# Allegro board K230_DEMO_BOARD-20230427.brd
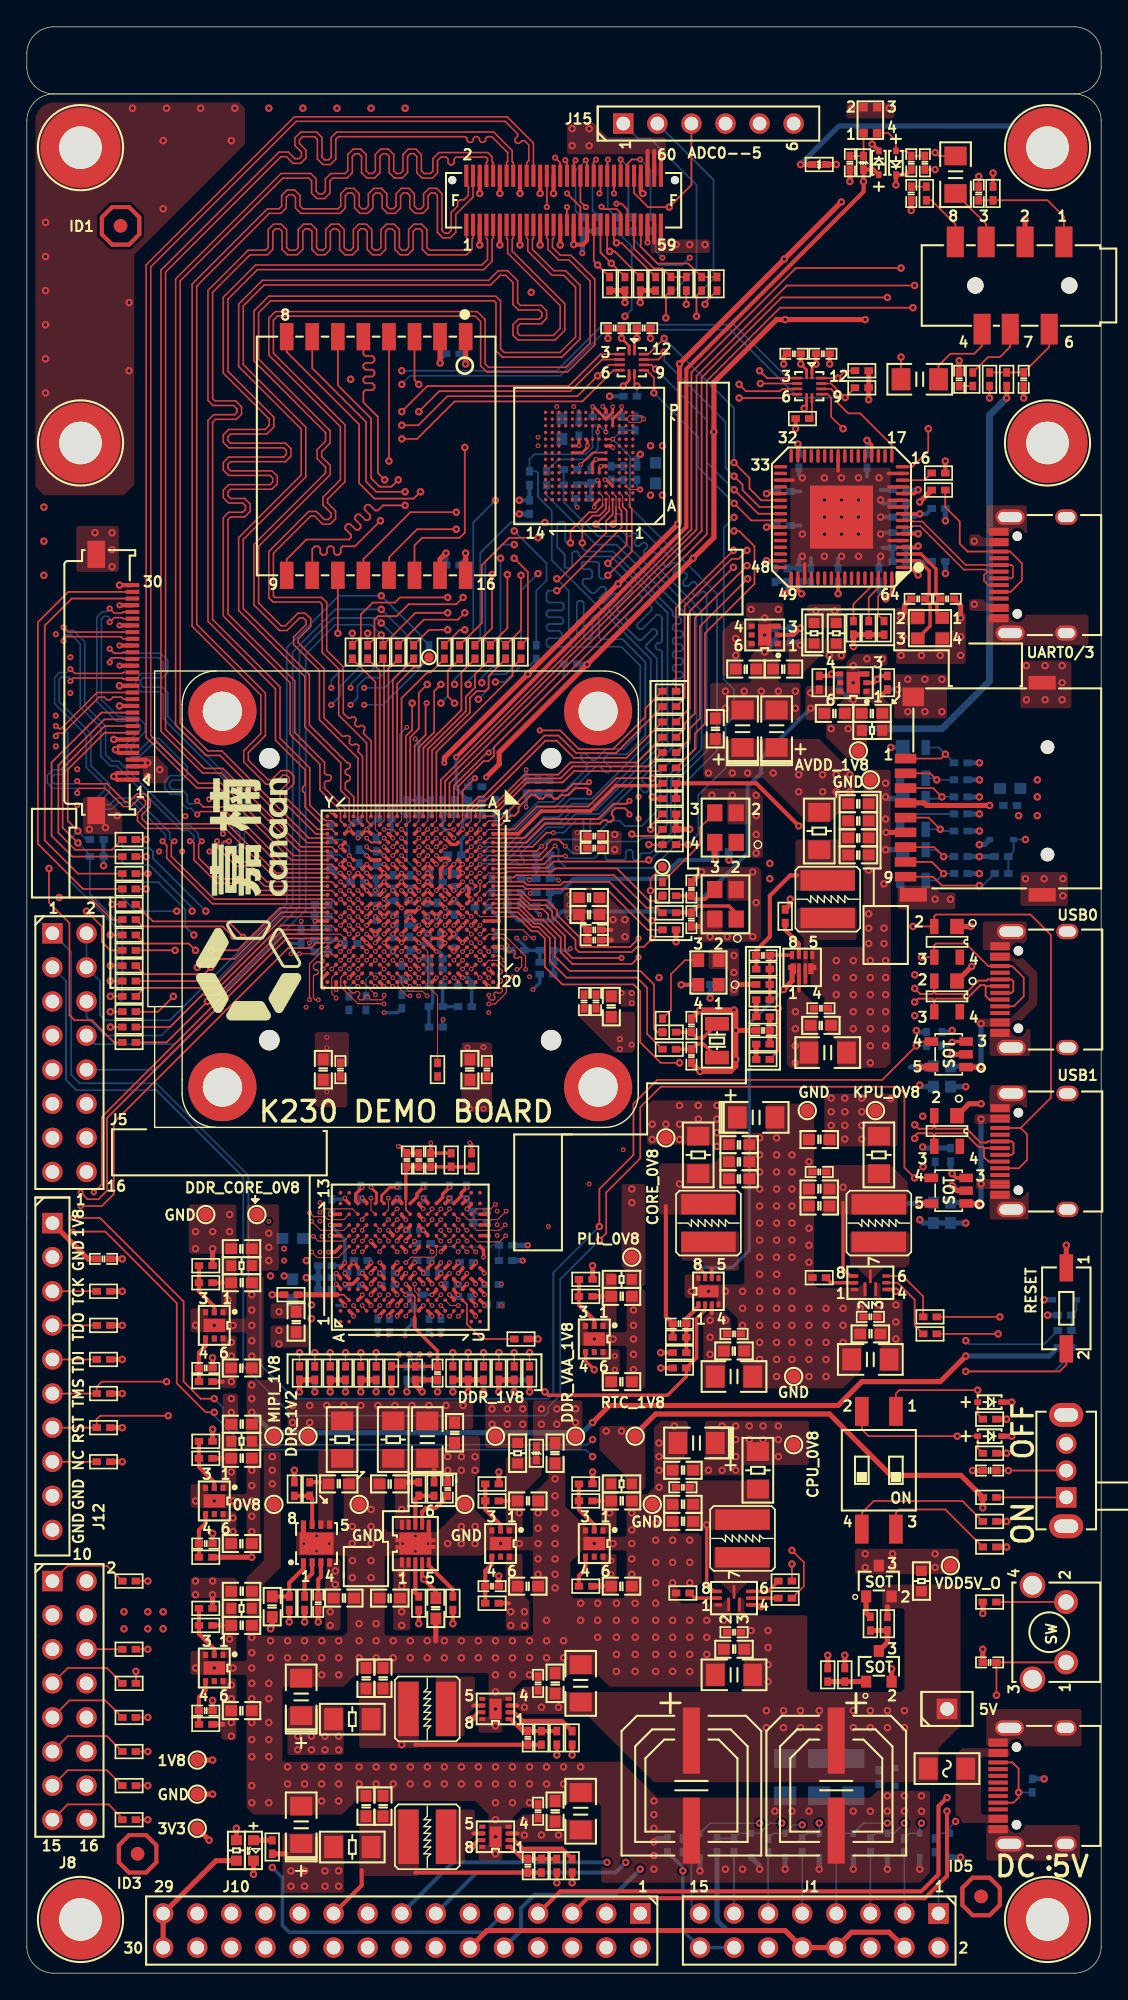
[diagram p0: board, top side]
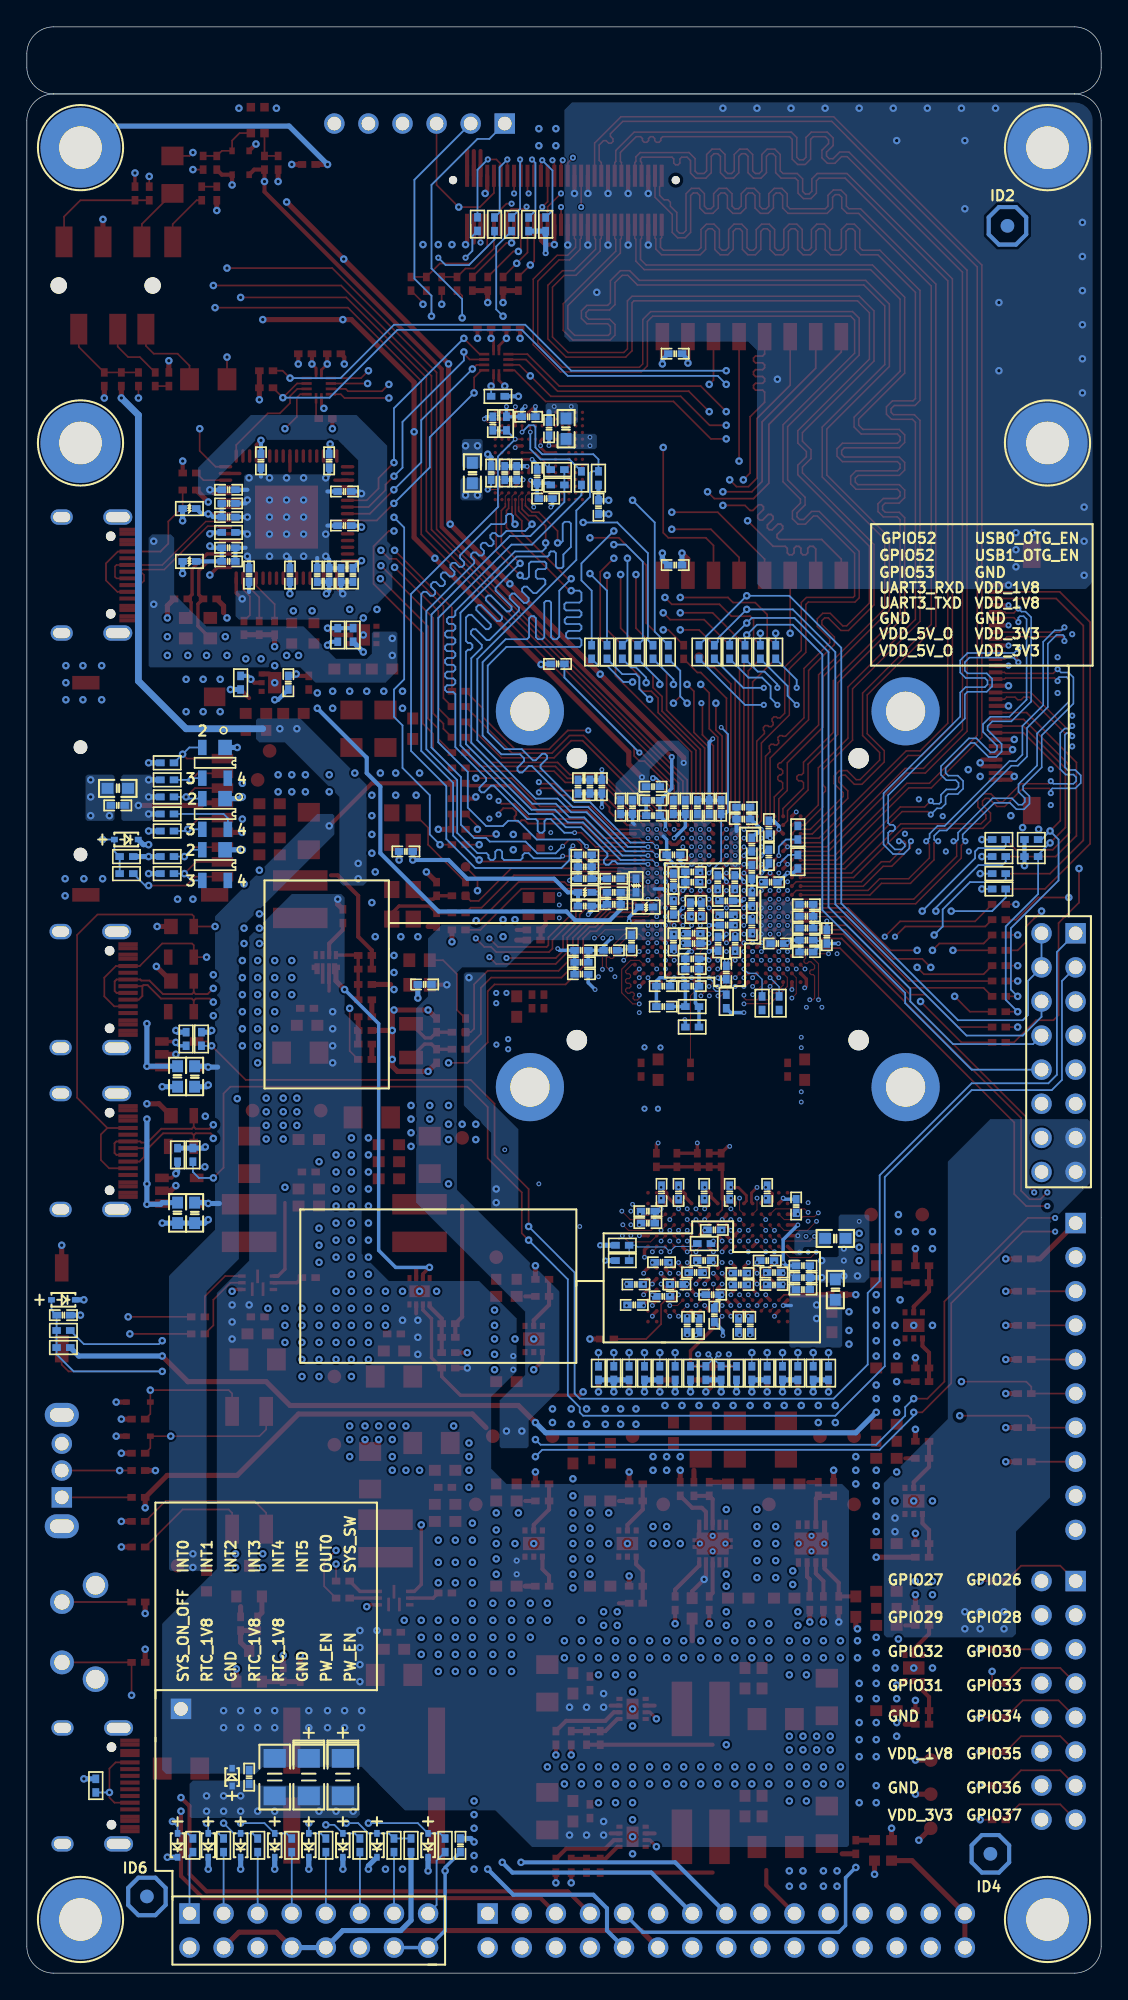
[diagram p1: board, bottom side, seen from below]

Outline 80.07 x 145 mm; copper layers: TOP, GND02, ART03, POWER04, GND05, ART06, GND07, BOTTOM. Coordinates in mm from the lower left corner of the outline.
Outline path: 2,140 arc(0.59,139.41) 0,138 0,2 arc(0.59,0.59) 2,0 78.07,0 arc(79.48,0.59) 80.07,2 80.07,138 arc(79.48,139.41) 78.07,140 ; 2,140 arc(0.59,140.59) 0,142 0,143 arc(0.59,144.41) 2,145 78.07,145 arc(79.48,144.41) 80.07,143 80.07,142 arc(79.48,140.59) 78.07,140 ; 2,140 78.07,140 ; 2,140 78.07,140

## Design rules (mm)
net group 3D_CTRL_IN: nets 3D_CTRL_IN N21013370
net group 3D_CTRL_OUT1: nets 3D_CTRL_OUT1 N21013374
net group 3D_CTRL_OUT2: nets 3D_CTRL_OUT2 N21013378
net group ADC_2: nets ADC_2 N21252475
net group ADC_3: nets ADC_3 N21252478
net group ADC_4: nets ADC_4 N21252481
net group BUS-ADD: nets LP3_CA0 LP3_CA1
net group DIFF100: nets DEBUG_DM DEBUG_DP
net group DL_M_CLK2: nets DL_M_CLK2 N21014154
net group DL_M_CLK3: nets DL_M_CLK3 N21014156
net group DP_M_CLK1: nets DP_M_CLK1 N21013382
net group EMMC_CLK: nets EMMC_CLK N21433380
net group EMMC_STROBE: nets EMMC_STROBE N21377535
net group GPIO26: nets GPIO26 N21015638
net group GPIO27: nets GPIO27 N21015640
net group GPIO28: nets GPIO28 N21015650
net group GPIO32: nets GPIO32 N21015658
net group GPIO33: nets GPIO33 N21015660
net group GPIO34: nets GPIO34 N21015662
net group GPIO35: nets GPIO35 N21015664
net group GPIO36: nets GPIO36 N21015666
net group GPIO37: nets GPIO37 N21015668
net group GPIO47: nets GPIO47 N21014397
net group GPIO48: nets GPIO48 N21014399
net group GPIO49: nets GPIO49 N21014401
net group GPIO52: nets GPIO52 N21015121
net group GPIO60_3V3: nets GPIO60_3V3 N21015137
net group GPIO61_3V3: nets GPIO61_3V3 N21015139
net group I2C3_SCL: nets I2C3_SCL N21014391
net group I2C3_SDA: nets I2C3_SDA N21014393
net group LP3_ODT: nets LP3_ODT N21376209
net group MMC1_CLK: nets MMC1_CLK N21015127
net group MMC1_CMD: nets MMC1_CMD N21015125
net group MMC1_D0: nets MMC1_D0 N21015129
net group MMC1_D1: nets MMC1_D1 N21015131
net group MMC1_D2: nets MMC1_D2 N21015133
net group MMC1_D3: nets MMC1_D3 N21015135
net group N21049039: nets N21049039 N21049045
net group N21049041: nets N21049041 N21049043
net group N21271073: nets N21271073 N21284561
net group RTC_CLK_OUT: nets N20962780 RTC_CLK_OUT
net group RTC_INT0: nets N21140162 RTC_INT0
net group RTC_INT1: nets N21140164 RTC_INT1
net group RTC_INT2: nets N21140180 RTC_INT2
net group RTC_INT3: nets N21140182 RTC_INT3
net group RTC_INT4: nets N21259420 RTC_INT4
net group RTC_INT5: nets N21259407 RTC_INT5
net group RTC_OUT0: nets N21259441 RTC_OUT0
net group RTC_OUT1: nets RTC_OUT1 SYS_RST
net group SYS_CLK_OUT: nets N20990759 SYS_CLK_OUT
net group SYS_SW: nets N21259446 SYS_SW
net group UART3_RXD: nets N21015111 UART3_RXD
net group UART3_TXD: nets N21015109 UART3_TXD
net group 18MIL: nets EMMC_RST JTAG_RST JTAG_TCK
net group ADC_0: nets ADC_0 HSY0 N21014379 N21252465 UART0_TXD
net group ADC_1: nets ADC_1 N21014381 N21252472 UART0_RXD VSY0
net group ADC_5: nets ADC_5 HP_INSERT_DET N21252484
net group DIFF90: nets USB0_DN USB0_DP USB1_DN USB1_DP
net group DP_RST: nets DP_RST GPIO46 N21014395
net group DP_STROBE: nets DP_STROBE GPIO42 N21014387
net group DP_VSYNC: nets DP_VSYNC GPIO43 N21014389 N21284570
net group GPIO9: nets GPIO9 LCD_RST N21013366
net group GPIO29: nets GPIO29 N21015652 TOUCH_INT
net group GPIO30: nets GPIO30 N21015654 TOUCH_RST
net group GPIO31: nets GPIO31 LCD_EN N21015656
net group GPIO53: nets GPIO53 N21015123 N21453086
net group I2C1_SCL: nets I2C1_SCL N21014383 N21299164
net group I2C1_SDA: nets I2C1_SDA N21014385 N21299161
net group I2C4_SCL: nets I2C4_SCL N21013358 N21299304
net group I2C4_SDA: nets I2C4_SDA N21013362 N21299301
net group RTC_CLK_IN: nets N20962765 N20962782 RTC_CLK_IN
net group SYS_CLK_IN: nets N20990697 N20990724 SYS_CLK_IN
net group U_3V3: nets N21611781

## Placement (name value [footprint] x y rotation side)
C1  100nF/16V  [C0402]  71.75 23.15 180 top
C2  100nF/16V  [C0402]  71.75 37.44 0 top
C3  12pF/50V  [C0402]  49.53 68.33 270 top
C4  12pF/50V  [C0402]  49.53 70.61 90 top
C5  100nF/16V  [C0402]  31.88 76.83 270 bottom
C6  100nF/16V  [C0402]  35 76.83 270 bottom
C7  100nF/16V  [C0402]  50.42 73.66 0 bottom
C8  12pF/50V  [C0402]  49.53 78.49 270 top
C9  22uF/16V-1206  [C1206]  61.59 14.61 270 bottom
C10  100nF/16V  [C0402]  51.82 83.57 0 bottom
C11  12pF/50V  [C0402]  49.53 80.77 90 top
C12  100nF/16V  [C0402]  63.5 14.61 270 bottom
C13  100nF/16V  [C0402]  77.34 49.02 0 bottom
C14  100nF/16V  [C0402]  31.88 83.31 180 bottom
C15  100nF/16V  [C0402]  34.92 86.87 90 bottom
C16  10uF/10V-0603  [C0603]  67.56 66.8 90 bottom
C17  10uF/10V-0603  [C0603]  68.83 66.8 270 bottom
C18  100nF/16V  [C0402]  41.15 115.06 90 bottom
C19  1uF/6.3V  [C0402]  44.45 111.76 270 bottom
C20  10uF/10V-0603  [C0603]  67.56 56.64 90 bottom
C21  10uF/10V-0603  [C0603]  68.83 56.64 270 bottom
C22  100nF/16V  [C0402]  43.56 111.76 270 bottom
C23  10uF/10V-0603  [C0603]  46.86 111.76 90 bottom
C24  100nF/16V  [C0402]  45.47 111.76 90 bottom
C25  100nF/16V  [C0402]  45.34 115.44 90 bottom
C26  100nF/16V  [C0402]  24.13 76.71 180 bottom
C27  100nF/16V  [C0402]  28.32 86.87 90 bottom
C28  100nF/16V  [C0402]  21.97 79.63 180 bottom
C29  100nF/16V  [C0402]  30.1 86.87 90 bottom
C30  100nF/16V  [C0402]  26.67 85.98 180 bottom
C31  100nF/16V  [C0402]  21.97 77.85 180 bottom
C32  100nF/16V  [C0402]  31.88 79.38 90 bottom
C33  10uF/10V-0603  [C0603]  41.91 80.14 0 top
C34  1uF/6.3V  [C0402]  42.29 76.96 0 top
C35  100nF/16V  [C0402]  38.48 81.53 180 bottom
C36  100nF/16V  [C0402]  38.73 76.2 0 bottom
C37  100nF/16V  [C0402]  36.58 76.2 180 bottom
C38  100nF/16V  [C0402]  28.57 81.28 270 bottom
C39  100nF/16V  [C0402]  27.3 81.28 270 bottom
C40  100nF/16V  [C0402]  27.94 79.88 180 bottom
C41  10uF/10V-0603  [C0603]  41.91 78.87 0 top
C42  1uF/6.3V  [C0402]  42.29 77.72 0 top
C43  100nF/16V  [C0402]  38.73 75.31 0 bottom
C44  100nF/16V  [C0402]  38.73 74.42 0 bottom
C45  100nF/16V  [C0402]  38.48 83.31 180 bottom
C46  100nF/16V  [C0402]  26.04 77.98 270 bottom
C47  100nF/16V  [C0402]  26.04 80.01 90 bottom
C48  100nF/16V  [C0402]  38.48 82.42 180 bottom
C49  10uF/10V-0603  [C0603]  51.31 92.71 90 top
C50  1uF/6.3V  [C0402]  42.29 83.82 0 top
C51  100nF/16V  [C0402]  42.29 84.71 0 top
C52  100nF/16V  [C0402]  30.48 81.28 0 bottom
C53  100nF/16V  [C0402]  38.99 88.39 90 bottom
C54  100nF/16V  [C0402]  38.1 88.39 90 bottom
C55  100nF/16V  [C0402]  37.21 88.39 90 bottom
C56  100nF/16V  [C0402]  30.48 82.04 0 bottom
C57  10uF/10V-0603  [C0603]  43.56 72.01 270 top
C58  1uF/6.3V  [C0402]  30.61 79.25 90 bottom
C59  100nF/16V  [C0402]  42.42 72.39 270 top
C60  100nF/16V  [C0402]  41.53 72.39 270 top
C61  100nF/16V  [C0402]  29.79 79.25 90 bottom
C62  NC  [C0402]  30.48 73.53 0 bottom
C63  10uF/10V-0603  [C0603]  22.1 67.31 270 top
C64  1uF/6.3V  [C0402]  23.37 67.31 270 top
C65  100nF/16V  [C0402]  21.97 76.96 0 bottom
C66  100nF/16V  [C0402]  21.97 76.07 0 bottom
C67  100nF/16V  [C0402]  27.91 78.84 180 bottom
C68  100nF/16V  [C0402]  27.91 78.08 0 bottom
C69  10uF/10V-0603  [C0603]  33.02 67.31 270 top
C70  1uF/6.3V  [C0402]  34.29 67.31 270 top
C71  100nF/16V  [C0402]  32.64 72.01 0 bottom
C72  100nF/16V  [C0402]  27.94 74.55 270 bottom
C73  100nF/16V  [C0402]  30.38 77.47 0 bottom
C74  100nF/16V  [C0402]  28.55 76.68 270 bottom
C75  100nF/16V  [C0402]  27.28 76.68 270 bottom
C76  1uF/6.3V  [C0402]  32.64 73.53 0 bottom
C77  100nF/16V  [C0402]  30.38 76.71 0 bottom
C78  1uF/6.3V  [C0402]  38.48 79.5 180 bottom
C79  100nF/16V  [C0402]  29.21 86.87 90 bottom
C80  100nF/16V  [C0402]  21.97 78.74 180 bottom
C81  1uF/6.3V  [C0402]  26.67 86.87 180 bottom
C82  100nF/16V  [C0402]  36.32 80.52 0 bottom
C83  1uF/6.3V  [C0402]  36.32 79.63 0 bottom
C84  100nF/16V  [C0402]  36.32 81.53 0 bottom
C85  1uF/6.3V  [C0402]  24.77 85.34 90 bottom
C86  100nF/16V  [C0402]  24.77 83.19 90 bottom
C87  100nF/16V  [C0402]  26.04 84.07 90 bottom
C88  1uF/6.3V  [C0402]  20.45 77.22 90 bottom
C89  100nF/16V  [C0402]  24.64 81.28 180 bottom
C90  100nF/16V  [C0402]  26.04 82.04 270 bottom
C91  100nF/16V  [C0402]  30.1 60.58 90 top
C92  100nF/16V  [C0402]  29.21 60.58 270 top
C93  10uF/10V-0603  [C0603]  20.07 48.51 90 top
C94  1uF/6.3V  [C0402]  24.89 58.17 270 bottom
C95  100nF/16V  [C0402]  29.97 48.26 270 bottom
C96  100nF/16V  [C0402]  26.15 48.26 270 bottom
C97  100nF/16V  [C0402]  31.62 51.31 180 bottom
C98  100nF/16V  [C0402]  32.64 50.42 0 bottom
C99  100nF/16V  [C0402]  28.83 55.37 0 bottom
C100  100nF/16V  [C0402]  31.5 58.17 90 bottom
C101  100nF/16V  [C0402]  32.77 58.17 90 bottom
C102  100nF/16V  [C0402]  29.59 58.17 90 bottom
C103  100nF/16V  [C0402]  27.04 48.26 270 bottom
C104  100nF/16V  [C0402]  30.86 48.26 270 bottom
C105  10uF/10V-0603  [C0603]  19.81 54.74 180 bottom
C106  1uF/6.3V  [C0402]  22.73 57.15 90 bottom
C107  100nF/16V  [C0402]  26.92 52.16 180 bottom
C108  100nF/16V  [C0402]  24.89 53.09 180 bottom
C109  100nF/16V  [C0402]  24.38 51.27 180 bottom
C110  100nF/16V  [C0402]  26.92 51.27 180 bottom
C111  100nF/16V  [C0402]  29.59 53.09 0 bottom
C112  100nF/16V  [C0402]  32.77 52.96 0 bottom
C113  100nF/16V  [C0402]  27.69 58.17 90 bottom
C114  100nF/16V  [C0402]  33.78 56.77 180 bottom
C115  100nF/16V  [C0402]  30.23 52.2 0 bottom
C116  100nF/16V  [C0402]  24.38 52.2 180 bottom
C117  10uF/10V-0603  [C0603]  19.81 50.93 90 bottom
C118  1uF/6.3V  [C0402]  22.23 50.93 180 bottom
C119  100nF/16V  [C0402]  33.78 55.88 180 bottom
C120  100nF/16V  [C0402]  34.67 51.31 0 bottom
C121  100nF/16V  [C0402]  22.23 52.7 180 bottom
C122  100nF/16V  [C0402]  34.8 49.78 0 bottom
C123  100nF/16V  [C0402]  22.23 51.82 180 bottom
C124  2.2uF/10V-0603  [C0603]  37.34 28.83 0 top
C125  22uF/6.3V-0603  [C0603]  37.34 35.18 180 top
C126  NC  [C0402]  34.67 28.83 0 top
C127  2.2uF/10V-0603  [C0603]  16 45.09 0 top
C128  22uF/6.3V-0603  [C0603]  16 51.44 180 top
C129  NC  [C0402]  13.34 45.09 0 top
C130  4.7uF/16V-0603  [C0603]  18.29 27.3 270 top
C131  22uF/6.3V-0603  [C0603]  23.24 36.45 180 top
C132  22uF/6.3V-0603  [C0603]  23.62 27.94 180 top
C133  1nF/50V  [C0402]  21.72 27.56 270 top
C134  2.2uF/10V-0603  [C0603]  44.32 28.83 0 top
C135  22uF/6.3V-0603  [C0603]  44.32 35.18 180 top
C136  100nF/16V  [C0402]  13.34 32 180 top
C137  2.2uF/10V-0603  [C0603]  44.32 44.07 0 top
C138  22uF/6.3V-0603  [C0603]  44.32 50.42 180 top
C139  100nF/16V  [C0402]  73.29 87 0 bottom
C140  2.2uF/10V-0603  [C0603]  16 19.56 0 top
C141  22uF/6.3V-0603  [C0603]  16 25.91 180 top
C142  NC  [C0402]  13.34 19.56 0 top
C143  2.2uF/10V-0603  [C0603]  16 32 0 top
C144  22uF/6.3V-0603  [C0603]  16 38.35 180 top
C145  22uF/6.3V-0603  [C0603]  73.29 88.27 0 bottom
C146  2.2uF/10V-0603  [C0603]  60.2 93.85 0 top
C147  22uF/6.3V-0603  [C0603]  62.99 93.85 0 top
C148  NC  [C0402]  60.58 96.14 270 bottom
C149  4.7uF/6.3V  [C0402]  31.88 86.87 90 bottom
C150  100nF/16V  [C0402]  30.99 86.87 90 bottom
C151  4.7uF/6.3V  [C0402]  35.81 86.87 90 bottom
C152  4.7uF/6.3V  [C0402]  33.4 86.23 0 bottom
C153  100nF/16V  [C0402]  33.4 87.38 0 bottom
C154  100nF/16V  [C0402]  33.4 88.39 0 bottom
C155  100nF/16V  [C0402]  61.34 134.87 270 top
C156  27pF/50V  [C0402]  65.91 134.87 270 top
C157  100nF/16V  [C0402]  70.94 132.59 270 top
C158  100nF/16V  [C0402]  65.91 132.59 90 top
C159  22uF/16V-1206  [C1206]  66.55 118.75 0 top
C160  100nF/16V  [C0402]  69.49 118.75 270 top
C161  22uF/16V-1206  [C1206]  69.22 133.99 270 top
C162  100nF/16V  [C0402]  74.3 118.75 270 top
C163  1nF/50V  [C0402]  31.37 36.07 90 top
C164  4.7uF/16V-0603  [C0603]  30.48 27.18 270 top
C165  22uF/16V-1206  [C1206]  41.27 21.59 90 top
C166  22uF/6.3V-0603  [C0603]  27.05 27.94 0 top
C167  22uF/6.3V-0603  [C0603]  27.05 36.45 0 top
C168  10uF/10V-0603  [C0603]  39.37 21.59 90 top
C169  100nF/16V  [C0402]  38.1 21.59 270 top
C170  22pF/50V  [C0402]  37.34 17.53 270 top
C171  22uF/6.3V-0603  [C0603]  26.54 21.97 90 top
C172  22uF/6.3V-0603  [C0603]  25.27 21.97 90 top
C173  22uF/16V-1206  [C1206]  59.69 68.58 0 top
C174  10uF/10V-0603  [C0603]  59.18 70.61 0 top
C175  100nF/16V  [C0402]  59.18 71.88 180 top
C176  22pF/50V  [C0402]  54.86 75.82 180 top
C177  22uF/6.3V-0603  [C0603]  61.98 83.31 0 top
C178  22uF/6.3V-0603  [C0603]  61.98 84.58 0 top
C179  22uF/6.3V-0603  [C0603]  61.98 85.85 0 top
C180  22uF/6.3V-0603  [C0603]  61.98 87.12 0 top
C187  22uF/16V-1206  [C1206]  52.7 44.45 0 top
C188  10uF/10V-0603  [C0603]  52.7 46.35 0 top
C189  100nF/16V  [C0402]  52.7 47.62 180 top
C190  22pF/50V  [C0402]  48.64 48.39 180 top
C191  22uF/6.3V-0603  [C0603]  53.09 59.18 0 top
C192  22uF/6.3V-0603  [C0603]  53.09 60.45 0 top
C193  22uF/16V-1206  [C1206]  41.27 12.06 90 top
C194  10uF/10V-0603  [C0603]  39.37 12.06 90 top
C195  100nF/16V  [C0402]  38.1 12.06 270 top
C196  22pF/50V  [C0402]  37.34 8 270 top
C197  22uF/6.3V-0603  [C0603]  25.27 12.45 90 top
C198  22uF/6.3V-0603  [C0603]  26.54 12.45 90 top
C199  4.7uF/6.3V  [C0402]  65.03 110.51 0 bottom
C200  100nF/16V  [C0402]  57.54 112.67 90 bottom
C201  12pF/50V  [C0402]  66.43 102.38 180 top
C202  100nF/16V  [C0402]  56.65 104.16 270 bottom
C203  4.7uF/6.3V  [C0402]  62.62 112.67 90 bottom
C204  12pF/50V  [C0402]  68.59 102.38 0 top
C205  100nF/16V  [C0402]  31.88 81.41 90 bottom
C206  100nF/16V  [C0402]  5.71 53.21 180 top
C207  100nF/16V  [C0402]  57.17 120.64 180 top
C208  100nF/16V  [C0402]  59.33 120.64 180 top
C209  22uF/16V-1206  [C1206]  62.87 45.72 180 top
C210  10uF/10V-0603  [C0603]  62.87 47.62 180 top
C211  100nF/16V  [C0402]  62.87 48.9 0 top
C212  22uF/6.3V-0603  [C0603]  59.05 57.15 180 top
C213  22uF/6.3V-0603  [C0603]  59.05 58.42 180 top
C214  100nF/16V  [C0402]  59.05 59.69 180 top
C215  22uF/6.3V-0603  [C0603]  59.05 62.1 180 top
C216  100nF/16V  [C0402]  58.43 104.16 270 bottom
C217  100nF/16V  [C0402]  57.54 104.16 270 bottom
C218  100nF/16V  [C0402]  60.46 104.16 270 bottom
C219  100nF/16V  [C0402]  56.4 107.84 180 bottom
C220  100nF/16V  [C0402]  55.76 104.16 270 bottom
C221  100nF/16V  [C0402]  56.4 110.38 180 bottom
C222  100nF/16V  [C0402]  63.51 104.16 270 bottom
C223  4.7uF/6.3V  [C0402]  65.03 108.48 180 bottom
C224  100nF/16V  [C0402]  65.03 109.49 180 bottom
C225  4.7uF/6.3V  [C0402]  65.03 106.19 180 bottom
C226  100nF/16V  [C0402]  65.03 105.18 180 bottom
C227  22uF/6.3V-0603  [C0603]  16 53.98 0 top
C228  22uF/16V-1206  [C1206]  52.7 22.23 180 top
C229  10uF/10V-0603  [C0603]  52.7 24.13 180 top
C230  100nF/16V  [C0402]  52.7 25.4 0 top
C231  22uF/6.3V-0603  [C0603]  48.9 33.66 180 top
C232  22uF/6.3V-0603  [C0603]  48.9 34.92 180 top
C233  100nF/16V  [C0402]  48.9 36.2 180 top
C234  22uF/6.3V-0603  [C0603]  48.9 37.47 180 top
C238  100nF/16V  [C0402]  40.51 97.54 0 bottom
C239  100nF/16V  [C0402]  54.86 70.23 180 top
C240  22uF/6.3V-0603  [C0603]  53.09 61.72 0 top
C241  22uF/6.3V-0603  [C0603]  31.88 40.26 90 top
C242  100nF/16V  [C0402]  31.75 120.65 0 bottom
C243  10uF/16V-1206  [TC1206]  20.45 11.05 90 top
C244  10uF/10V-0603  [C0603]  39.88 115.06 270 bottom
C245  2.2uF/10V-0603  [C0603]  16 40.89 180 top
C246  2.2uF/10V-0603  [C0603]  16 28.45 180 top
C247  330uF/25V  [C1010_8383_6666]  49.53 13.97 180 top
C248  330uF/25V  [C1010_8383_6666]  60.33 13.97 180 top
C249  10uF/16V-1206  [TC1206]  59.05 14.61 270 bottom
C250  10uF/16V-1206  [TC1206]  56.52 14.61 270 bottom
C251  10uF/16V-1206  [TC1206]  54.36 63.75 0 top
C252  10uF/16V-1206  [TC1206]  55.88 92.71 90 top
C253  10uF/16V-1206  [TC1206]  49.91 39.5 180 top
C254  10uF/16V-1206  [TC1206]  53.34 92.71 90 top
C255  10uF/16V-1206  [TC1206]  20.45 20.57 90 top
C256  1uF/6.3V  [C0402]  41.4 109.86 180 bottom
C257  100nF/16V  [C0402]  42.67 115.95 180 bottom
C258  100nF/16V  [C0402]  42.04 111.51 90 bottom
C259  100nF/16V  [C0402]  37.47 109.22 270 bottom
C260  100nF/16V  [C0402]  31.75 104.9 180 bottom
C261  NC  [C0402]  30.48 74.8 180 bottom
C262  NC  [C0402]  30.48 75.56 0 bottom
C263  1nF/50V  [C0402]  28.32 60.58 90 top
C264  NC  [C0402]  30.61 44.7 270 top
C265  100nF/16V  [C0402]  28.83 49.02 90 bottom
C266  1nF/50V  [C0402]  28.96 50.55 0 bottom
C267  NC  [C1206]  29.84 39.75 270 top
C268  NC  [C0402]  47.75 9.53 90 bottom
C269  10uF/10V-0603  [C0603]  39.37 38.73 270 top
C270  100nF/16V  [C0402]  66.93 134.87 270 top
C271  100nF/16V  [C0402]  45.97 122.56 0 top
C272  100nF/16V  [C0402]  43.81 122.56 0 top
C273  2.2uF/10V-0603  [C0603]  53.59 97.16 0 top
C274  22uF/6.3V-0603  [C0603]  56.39 97.16 0 top
D1  NC  [SOD523-2-28-H]  64.77 14.61 90 bottom
F1  3A-12V  [F1206]  68.58 15.24 180 top
FB1  600R/100MHz-500mA  [FB0402]  59.05 134.75 180 top
FB2  600R/100MHz-500mA  [FB0402]  33.91 79.43 0 bottom
FB3  600R/100MHz-500mA  [FB0402]  37.97 38.73 90 top
FB4  600R/100MHz-500mA  [FB0402]  34.67 81.03 270 bottom
FB5  600R/100MHz-500mA  [FB0402]  38.48 80.52 0 bottom
FB6  600R/100MHz-500mA  [FB0402]  62.36 134.87 90 top
FB7  600R/100MHz-500mA  [FB0402]  67.95 105.18 180 bottom
FB8  600R/100MHz-500mA  [FB0402]  67.95 109.11 180 bottom
GPIO25  TEST POINT SMD circle 35 mils  [TP28]  29.97 98.04 0 top
ID1  -  [unnamed#2]  6.99 130.18 0 top
ID2  -  [unnamed#2]  6.99 130.18 180 bottom
ID3  -  [unnamed#2]  8.26 8.89 0 top
ID4  -  [unnamed#2]  8.26 8.89 180 bottom
ID5  -  [unnamed#2]  71.12 5.71 0 top
ID6  -  [unnamed#2]  71.12 5.71 180 bottom
J1  2X8_2.54mm  [HEAD2X8-100]  67.94 4.45 180 top
J2  TYPE-C  [TYPE-C-USB16-20-126-H-SMD-B]  76.36 13.95 90 top
J3  TH243-G60S-W0R01  [BTB2X30-050-F-SMD]  40.01 132.08 0 top
J4  FPC-05F-30PH20  [FPC30-005-0520-75]  7.87 96.16 270 top
J5  2X8_2.54mm  [HEAD2X8-100]  1.91 77.47 270 top
J6  TYPE-C  [TYPE-C-USB16-20-126-H-SMD-B]  76.42 104.16 90 top
J7  PJ35367  [AUDIO-PJ3536-7-197]  74.3 125.73 270 top
J8  2X8_2.54mm  [HEAD2X8-100]  1.91 29.21 270 top
J9  Flash-EXT  [SOP16-75]  26.04 113.03 270 top
J10  2x15PIN_2P54  [HEAD2X15-100]  45.72 4.45 180 top
J11  TYPE-C  [TYPE-C-USB16-20-126-H-SMD-B]  76.5 73.28 90 top
J12  10pin 2.54mm  [HEAD10-100]  1.91 48.26 270 top
J13  TYPE-C  [TYPE-C-USB16-20-126-H-SMD-B]  76.5 61.21 90 top
J15  NC  [HEAD6-100]  44.45 137.79 0 top
K1  KH-6X6X8H-ZJ  [DSW4-KH-6X6X7H-ZJ]  76.2 25.4 90 top
K2  TS-KG07U  [SW2-061036-025]  77.47 49.53 90 top
K3  SK12D07VG3  [DSW3-087044-047-H]  77.46 37.44 90 top
L1  0.47uH/6.4A  [PL0404-028]  63.5 55.88 270 top
L2  0.47uH/6.4A  [PL0404-028]  59.69 80.01 270 top
L3  0.47uH/6.4A  [PL0404-028]  53.34 32.38 270 top
L6  2.2uH/4.3A  [PL0404-028]  29.84 19.68 0 top
L9  2.2uH/4.3A  [PL0404-028]  50.8 55.88 270 top
L10  2.2uH/4.3A  [PL0404-028]  29.84 10.16 0 top
LED1  RED 0603  [LED0603]  16.89 9.14 270 top
M1  M3  [HOLE-M3]  76.07 4 90 top
M2  M3  [HOLE-M3]  4 136 90 top
M3  M3  [HOLE-M3]  76.07 136 90 top
M4  M3  [HOLE-M3]  4 114 90 top
M5  M3  [HOLE-M3]  76.07 114 90 top
M6  M3  [HOLE-M3]  4 4 90 top
NOREF  -  []  164.47 96.52 0 top
NOREF#2  -  [unnamed#3]  28.57 80.01 270 top
Q1  YJL2301C  [SOT23-3-43]  63.5 29.21 0 top
Q2  2N7002  [SOT23-3-43]  63.5 22.86 0 top
R1  0R  [R0402]  67.69 9.53 270 bottom
R2  0R  [R0402]  65.41 9.53 270 bottom
R3  0R  [R0402]  62.87 9.53 270 bottom
R4  0R  [R0402]  60.33 9.53 270 bottom
R5  0R  [R0402]  47.88 68.83 0 top
R6  0R  [R0402]  47.88 70.1 180 top
R7  NC  [R0402]  47.37 70.61 270 top
R8  0R  [R0402]  47.88 78.99 180 top
R9  5.1K/1%  [R0402]  74.93 13.97 90 bottom
R10  0R  [R0402]  47.88 80.26 180 top
R11  NC  [R0402]  47.37 80.77 270 top
R12  0R  [R0402]  57.78 9.53 270 bottom
R13  0R  [R0402]  71.75 31.75 0 top
R14  0R  [R0402]  71.75 33.66 0 top
R15  0R  [R0402]  55.24 9.53 270 bottom
R16  0R  [R0402]  52.7 9.53 270 bottom
R17  0R  [R0402]  48.9 9.53 270 bottom
R18  10K  [R0402]  71.75 41.27 0 top
R19  200R/1%  [R0402]  18.29 9.4 90 top
R20  10K  [R0402]  71.75 38.73 0 top
R21  0R-0603  [R0603]  36.58 38.73 90 top
R22  NC  [R0402]  77.34 47.88 0 bottom
R23  4.7K  [R0402]  44.96 117.47 180 bottom
R24  0R-1206  [R1206]  27.3 39.75 90 top
R25  0R  [R0402]  47.88 90.93 180 top
R26  0R  [R0402]  47.88 93.22 180 top
R27  0R  [R0402]  47.88 89.79 180 top
R28  0R  [R0402]  47.88 95.5 180 top
R29  0R  [R0402]  47.88 92.08 180 top
R30  0R  [R0402]  47.88 94.36 180 top
R31  2K/1%  [R0402]  72.01 132.59 270 top
R32  0R-0603  [R0603]  16 52.7 0 top
R33  0R  [R0402]  67.04 132.59 270 top
R34  0R  [R0402]  70.5 118.75 90 top
R35  10K  [R0402]  73.03 118.75 90 top
R36  10K  [R0402]  31.75 27.56 90 top
R37  4.99K/1%  [R0402]  30.35 36.07 270 top
R38  2.49K/1%  [R0402]  29.21 36.07 270 top
R39  30K/1%  [R0402]  47.88 87.5 0 top
R40  10K  [R0402]  68.2 69.6 270 bottom
R41  10K  [R0402]  67.06 69.6 90 bottom
R42  200R/1%  [R0402]  47.88 86.36 0 top
R43  30K/1%  [R0402]  47.88 88.65 0 top
R44  200R/1%  [R0402]  47.88 85.22 0 top
R45  10K  [R0402]  68.83 60.96 270 bottom
R46  10K  [R0402]  67.69 60.96 90 bottom
R47  0R  [R0402]  40.51 112.01 0 bottom
R48  10K  [R0402]  37.47 111.38 270 bottom
R49  10K  [R0402]  44.32 115.44 90 bottom
R50  0R  [R0402]  38.73 111.38 90 bottom
R51  0R  [R0402]  48.01 125.86 90 top
R52  0R  [R0402]  50.29 125.86 90 top
R53  NC  [R0402]  49.15 125.86 270 top
R54  NC  [R0402]  51.44 125.86 270 top
R55  0R  [R0402]  72.64 81.92 0 bottom
R56  200R/1%  [R0402]  22.61 82.8 90 bottom
R57  NC  [R0402]  30.48 72.01 180 bottom
R58  NC  [R0402]  30.48 70.48 0 bottom
R59  NC  [R0402]  40.51 110.87 0 bottom
R60  0R-1206  [R1206]  63.5 60.96 90 top
R61  240R/1%  [R0402]  27.94 72.39 270 bottom
R62  10K  [R0402]  51.44 9.53 270 bottom
R63  240R/1%  [R0402]  19.68 50.55 0 top
R64  0R  [R0402]  29.59 54.36 180 bottom
R65  NC  [R0402]  22.61 84.96 270 bottom
R66  100R/1%  [R0402]  31.62 60.58 90 top
R67  200R/1%  [R0402]  33.15 60.58 90 top
R68  1K/1%  [R0402]  28.96 44.7 90 top
R69  1K/1%  [R0402]  27.18 44.7 270 top
R70  100R/1%  [R0402]  30.61 44.7 90 bottom
R71  100R/1%  [R0402]  29.46 44.7 90 bottom
R72  100R/1%  [R0402]  28.32 44.7 90 bottom
R73  100R/1%  [R0402]  27.18 44.7 90 bottom
R74  100R/1%  [R0402]  31.75 44.7 90 bottom
R75  100R/1%  [R0402]  31.75 44.7 90 top
R76  100R/1%  [R0402]  26.04 44.7 90 bottom
R77  0R  [R0402]  7.62 72.77 0 top
R78  100R/1%  [R0402]  26.04 44.7 90 top
R79  0R  [R0402]  7.62 71.63 0 top
R80  100R/1%  [R0402]  35.69 53.09 180 bottom
R81  0R  [R0402]  7.62 81.92 180 bottom
R82  100R/1%  [R0402]  35.69 54.23 180 bottom
R83  0R  [R0402]  7.62 77.34 0 top
R84  100R/1%  [R0402]  36.32 44.7 90 bottom
R85  0R  [R0402]  7.62 70.48 0 top
R86  100R/1%  [R0402]  36.32 44.7 90 top
R87  0R  [R0402]  7.62 78.49 0 top
R88  100R/1%  [R0402]  34.04 44.7 90 bottom
R89  0R  [R0402]  7.62 76.2 0 top
R90  100R/1%  [R0402]  34.04 44.7 90 top
R91  0R  [R0402]  7.62 29.21 0 top
R92  0R  [R0402]  32.26 98.42 90 top
R93  0R  [R0402]  7.62 73.91 0 top
R94  0R  [R0402]  33.4 98.42 90 bottom
R95  0R  [R0402]  7.62 75.06 0 top
R96  0R  [R0402]  34.54 98.42 90 top
R97  0R  [R0402]  7.62 84.45 180 bottom
R98  0R  [R0402]  33.4 98.42 90 top
R99  0R  [R0402]  7.62 83.19 180 bottom
R100  0R  [R0402]  35.69 98.42 90 top
R101  0R  [R0402]  7.62 80.77 180 bottom
R102  0R  [R0402]  47.88 84.07 0 top
R103  0R  [R0402]  7.62 24.13 0 top
R104  0R  [R0402]  36.83 98.42 90 top
R105  0R  [R0402]  7.62 21.59 0 top
R106  0R  [R0402]  35.69 98.42 90 bottom
R107  0R  [R0402]  7.62 19.05 0 top
R108  0R  [R0402]  36.83 98.42 90 bottom
R109  0R  [R0402]  7.62 16.51 0 top
R110  0R  [R0402]  32.26 98.42 90 bottom
R111  0R  [R0402]  7.62 13.97 0 top
R112  0R  [R0402]  34.54 98.42 90 bottom
R113  0R  [R0402]  7.62 11.43 0 top
R114  0R  [R0402]  37.97 98.42 90 bottom
R115  0R  [R0402]  26.54 98.42 270 bottom
R116  0R  [R0402]  7.62 79.63 180 top
R117  0R  [R0402]  27.69 98.42 270 bottom
R118  0R  [R0402]  7.62 69.34 180 top
R119  0R  [R0402]  29.97 98.42 270 bottom
R120  0R  [R0402]  28.83 98.42 270 bottom
R121  0R  [R0402]  31.11 98.42 270 top
R122  0R  [R0402]  28.83 98.42 270 top
R123  0R  [R0402]  24.26 98.42 270 top
R124  0R  [R0402]  27.69 98.42 270 top
R125  0R  [R0402]  25.4 98.42 270 top
R126  0R  [R0402]  26.54 98.42 270 top
R127  0R  [R0402]  24.26 98.42 270 bottom
R128  0R  [R0402]  25.4 98.42 270 bottom
R129  100R/1%  [R0402]  32.89 44.7 90 bottom
R130  100R/1%  [R0402]  32.89 44.7 90 top
R131  100R/1%  [R0402]  37.47 44.7 90 bottom
R132  100R/1%  [R0402]  37.47 44.7 90 top
R133  100R/1%  [R0402]  35.18 44.7 90 bottom
R134  100R/1%  [R0402]  35.18 44.7 90 top
R135  0R-0603  [R0603]  16 27.18 0 top
R136  10.2K/1%  [R0402]  13.34 25.91 180 top
R137  5.1K/1%  [R0402]  64.14 26.04 90 top
R138  23.2K/1%  [R0402]  34.67 35.18 0 top
R139  10K  [R0402]  34.67 27.56 180 top
R140  10.2K/1%  [R0402]  34.67 36.45 0 top
R141  100R/1%  [R0402]  24.89 44.7 90 bottom
R142  0R-0603  [R0603]  44.32 36.45 0 top
R143  10K  [R0402]  13.34 44.07 180 top
R144  10K  [R0402]  13.34 30.99 180 top
R145  NC  [R1206]  23.5 39.75 90 top
R146  4.99K/1%  [R0402]  19.94 36.07 270 top
R147  4.22K/1%  [R0402]  21.08 36.07 270 top
R148  0R  [R0402]  20.7 27.56 270 top
R149  200K/1%  [R0402]  38.35 17.53 270 top
R150  10K  [R0402]  71.75 35.44 180 top
R151  10K  [R0402]  48.64 45.09 0 top
R152  66.5K/1%  [R0402]  54.86 74.8 180 top
R153  10K  [R0402]  40.64 17.53 90 top
R154  0R-0603  [R0603]  44.32 51.69 0 top
R155  10.2K/1%  [R0402]  41.66 50.42 180 top
R156  10K  [R0402]  40.64 8 90 top
R157  22.6K/1%  [R0402]  41.66 51.69 0 top
R158  10K  [R0402]  13.34 18.54 180 top
R159  22.6K/1%  [R0402]  13.34 27.18 0 top
R160  0R-0603  [R0603]  16 39.62 0 top
R161  23.2K/1%  [R0402]  13.34 38.35 0 top
R162  10K  [R0402]  69.61 87.63 180 bottom
R163  10.2K/1%  [R0402]  13.34 39.62 0 top
R164  0R-0603  [R0603]  62.99 92.58 180 top
R165  23.2K/1%  [R0402]  64.14 96.14 270 top
R166  10K  [R0402]  59.05 96.14 90 top
R167  10.2K/1%  [R0402]  64.14 96.14 270 bottom
R168  10K  [R0402]  29.21 27.56 270 top
R169  450K/1%  [R0402]  38.35 8 270 top
R170  100K/1%  [R0402]  39.5 17.53 90 top
R171  NC  [R0402]  54.86 69.22 180 top
R172  10K  [R0402]  56.52 78.74 270 top
R174  66.5K/1%  [R0402]  48.64 47.37 180 top
R175  200K/1%  [R0402]  54.86 73.66 180 top
R176  200K/1%  [R0402]  48.64 46.23 180 top
R177  10.2K/1%  [R0402]  13.34 51.44 180 top
R178  22.6K/1%  [R0402]  13.34 52.7 0 top
R179  0R  [R0402]  43.94 130.29 270 bottom
R180  0R  [R0402]  45.21 130.29 270 bottom
R181  0R  [R0402]  46.48 130.3 270 bottom
R182  0R  [R0402]  7.62 84.45 0 top
R183  0R  [R0402]  7.62 83.19 0 top
R184  0R  [R0402]  7.62 81.92 0 top
R185  23.2K/1%  [R0402]  41.66 35.18 0 top
R186  10K  [R0402]  41.66 28.83 180 top
R187  10.2K/1%  [R0402]  41.66 36.45 0 top
R188  10K  [R0402]  69.61 85.09 180 bottom
R189  10K  [R0402]  69.61 83.19 180 bottom
R190  10K  [R0402]  69.61 81.92 180 bottom
R191  10K  [R0402]  69.61 90.17 180 bottom
R192  100K/1%  [R0402]  39.5 8 90 top
R193  10K  [R0402]  69.61 88.9 180 bottom
R194  10K  [R0402]  72.64 83.19 0 bottom
R195  5.1K/1%  [R0402]  67.94 110.49 180 top
R196  NC  [R0603]  60.33 99.82 90 top
R197  10K  [R0402]  5.71 50.8 180 top
R198  NC  [R0402]  5.71 48.26 180 top
R199  10K  [R0402]  5.71 45.72 180 top
R200  10K  [R0402]  5.71 43.18 180 top
R201  10K  [R0402]  67.94 111.76 180 top
R202  12K/1%  [R0402]  65.03 107.34 0 bottom
R203  10K  [R0402]  63.89 100.22 90 top
R204  10K  [R0402]  62.75 100.22 90 top
R205  10K  [R0402]  61.6 100.22 90 top
R206  10K  [R0402]  5.71 40.64 180 top
R207  10K  [R0402]  5.71 38.1 180 top
R208  0R  [R0402]  7.62 80.77 0 top
R209  4.7K  [R0402]  57.81 115.82 0 top
R210  0R-1206  [R1206]  24.26 9.4 180 top
R211  56.2K/1%  [R0402]  59.05 51.82 180 top
R212  0R-1206  [R1206]  24.26 18.92 180 top
R213  NC  [R1206]  59.05 85.09 90 top
R214  0R-1206  [R1206]  54.48 37.47 90 top
R215  56.2K/1%  [R0402]  48.9 28.32 180 top
R217  0R  [R0402]  67.31 47.62 180 top
R218  0R-1206  [R1206]  50.04 60.96 90 top
R219  0R  [R0402]  67.31 48.9 180 top
R220  0R  [R0402]  56.52 27.94 180 top
R221  0R  [R0402]  71.75 118.75 90 top
R222  0R-0603  [R0603]  15.62 9.14 90 top
R223  10K  [R0402]  77.34 46.61 180 bottom
R224  100K/1%  [R0402]  56.9 99.69 270 bottom
R229  NC  [R0402]  54.86 72.52 180 top
R230  20K/1%  [R0402]  54.86 71.25 0 top
R232  NC  [R0402]  54.86 68.07 0 top
R233  0R  [R0402]  56.52 29.21 180 top
R234  4.7K  [R0402]  41.4 130.29 90 bottom
R235  4.7K  [R0402]  42.67 130.29 90 bottom
R236  4.7K  [R0402]  5.21 84.45 180 bottom
R237  4.7K  [R0402]  5.21 83.19 180 bottom
R238  4.7K  [R0402]  43.43 125.86 90 top
R239  4.7K  [R0402]  44.58 125.86 90 top
R240  4.7K  [R0402]  45.72 125.86 90 top
R241  4.7K  [R0402]  46.86 125.86 90 top
R242  4.7K  [R0402]  62.23 119.38 180 top
R243  4.7K  [R0402]  62.23 118.11 180 top
R244  20K/1%  [R0402]  55.75 99.69 270 bottom
R245  0R  [R0402]  69.61 86.36 0 bottom
R246  NC  [R0402]  19.56 27.56 90 top
R248  NC  [R0402]  24 72.26 270 bottom
R249  NC  [R0402]  25.27 72.26 270 bottom
R250  NC  [R0402]  30.61 67.31 270 top
R251  NC  [R0402]  36.83 47.24 0 top
R252  10K  [R0402]  47.88 77.72 180 top
R253  100R/1%  [R0402]  24.89 44.7 90 top
R254  100R/1%  [R0402]  22.61 44.7 90 bottom
R255  100R/1%  [R0402]  22.61 44.7 90 top
R256  100R/1%  [R0402]  23.75 44.7 90 bottom
R257  100R/1%  [R0402]  23.75 44.7 90 top
R258  100R/1%  [R0402]  21.46 44.7 90 bottom
R259  100R/1%  [R0402]  21.46 44.7 90 top
R260  100R/1%  [R0402]  20.32 44.7 90 bottom
R261  100R/1%  [R0402]  20.32 44.7 90 top
R262  10K  [R0402]  71.75 27.65 180 top
R263  0R  [R0402]  62.87 26.04 90 top
R264  NC  [R0603]  66.67 29.21 90 top
R265  0R  [R0402]  59.69 22.23 270 top
R266  200K/1%  [R0402]  60.96 22.23 270 top
R267  0R-0603  [R0603]  58.67 99.82 90 top
SW1  KF1027B-02P-G00-ON-01B  [SW4-100-060050-035]  63.5 37.47 180 top
TP1  DI  [TP40]  34.92 40.01 0 top
TP2  DI  [TP40]  12.7 15.88 0 top
TP3  DI  [TP40]  12.7 13.34 0 top
TP4  DI  [TP40]  40.89 40.01 0 top
TP5  DI  [TP40]  12.7 10.79 0 top
TP6  DI  [TP40]  24.77 34.92 0 top
TP7  DI  [TP40]  17.14 56.52 0 top
TP8  DI  [TP40]  13.34 56.52 0 top
TP9  DI  [TP40]  61.98 91.06 0 top
TP10  DI  [TP40]  20.95 40.01 0 top
TP11  DI  [TP40]  58.17 64.26 0 top
TP12  DI  [TP40]  18.41 40.01 0 top
TP13  DI  [TP40]  32.64 34.92 0 top
TP14  DI  [TP40]  47.62 62.23 0 top
TP15  DI  [TP40]  45.34 40.01 0 top
TP16  DI  [TP40]  46.61 34.92 0 top
TP17  DI  [TP40]  57.15 39.37 0 top
TP18  DI  [TP40]  18.41 34.92 0 top
TP19  DI  [TP40]  62.87 88.9 0 top
TP20  DI  [TP40]  45.09 53.34 0 top
TP21  DI  [HEAD-100]  68.58 19.68 0 top
TP22  DI  [TP40]  57.15 44.45 0 top
TP23  DI  [TP40]  63.25 64.26 0 top
TP24  DI  [TP40]  68.83 30.35 0 top
TVS1  ESD5B5.0ST1G  [SOD523-2-28]  68.83 9.53 270 bottom
TVS2  ESD5B5.0ST1G  [SOD523-2-28]  66.55 9.53 270 bottom
TVS3  ESD5B5.0ST1G  [SOD523-2-28]  77.34 50.16 180 bottom
TVS4  ESD5B5.0ST1G  [SOD523-2-28]  71.75 42.55 0 top
TVS5  ESD5B5.0ST1G  [SOD523-2-28]  71.75 40.01 0 top
TVS6  ESD5B5.0ST1G  [SOD523-2-28]  64.14 9.53 270 bottom
TVS7  ESD5B5.0ST1G  [SOD523-2-28]  61.59 9.53 270 bottom
TVS8  ESD5B5.0ST1G  [SOD523-2-28]  59.05 9.53 270 bottom
TVS9  ESD5B5.0ST1G  [SOD523-2-28]  56.52 9.53 270 bottom
TVS10  ESD5B5.0ST1G  [SOD523-2-28]  53.98 9.53 270 bottom
TVS11  ESD5B5.0ST1G  [SOD523-2-28]  50.16 9.53 270 bottom
TVS12  ESD5B5.0ST1G  [SOD523-2-28]  72.66 84.45 180 bottom
TVS13  ESD5B5.0ST1G  [SOD523-2-28]  63.5 134.87 90 top
TVS14  ESD5B5.0ST1G  [SOD523-2-28]  64.77 134.87 270 top
U1  K230-USIP  [BBGA390-065-1313-020]  28.57 80.01 270 top
U2  TLV75801PDRVR  [DFN6-065-0202-008-N]  42.29 32 270 top
U3  DIO7002AST5  [SOT23-5-36]  68.71 68.45 90 top
U4  TF-01A  [CARD-MICRO-SD-9-80]  73.42 88.27 90 top
U5  NT6CL128M32DM-H0  [BGA178-080065-120115-008]  28.57 53.34 90 top
U6  DIO7002AST5  [SOT23-5-36]  68.71 58.29 90 top
U7  MSM381ACT001  [MIC4-028019-010]  62.87 138.05 180 top
U8  TLV75801PDRVR  [DFN6-065-0202-008-N]  35.31 32 270 top
U9  TLV75801PDRVR  [DFN6-065-0202-008-N]  13.97 48.26 270 top
U10  TPS7A7401DSDR/NC  [WSON8-065-0303-008-N]  21.59 32 90 top
U11  TPS74801DRC  [DFN10-050-0303-010-N]  28.96 32 90 top
U12  TLV75801PDRVR  [DFN6-065-0202-008-N]  42.29 47.24 270 top
U13  TLV75801PDRVR  [DFN6-065-0202-008-N]  13.97 22.73 270 top
U14  TLV75801PDRVR  [DFN6-065-0202-008-N]  13.97 35.18 270 top
U15  TLV75801PDRVR  [DFN6-065-0202-008-N]  61.59 96.14 180 top
U16  SGM4574YUQN12G  [QFN12-040-018018-006]  45.09 120.02 270 top
U17  SY8003EDFC  [QFN8-050-0202-008-N]  34.92 19.68 90 top
U18  SY8876DFC  [DFN8-050-0202-006]  57.78 74.93 0 top
U20  SY8003EDFC  [QFN8-050-0202-008-N]  50.8 50.8 0 top
U21  SY8003EDFC  [QFN8-050-0202-008-N]  34.92 10.16 90 top
U22  PRTR5V0U2X  [SOT143-4-48]  66.04 86.36 0 bottom
U23  PRTR5V0U2X  [SOT143-4-48]  66.04 82.55 0 bottom
U24  PRTR5V0U2X  [SOT143-4-48]  66.04 90.17 0 bottom
U25  SGM4574YUQN12G  [QFN12-040-018018-006]  58.31 118.23 270 top
U26  FT2232HQ  [QFN64-050-0909-010-N]  60.71 108.48 180 top
U27  TPS628681A  [QFN9-050-025015-010]  62.87 51.44 90 top
U28  TPS628681A  [QFN9-050-025015-010]  52.7 27.94 90 top
U29  TLV75801PDRVR  [DFN6-065-0202-008-N]  54.99 99.69 180 top
U30  KLM4G1FETE-B041  [BGA153-050-011010-008]  41.91 113.03 180 top
U31  PRTR5V0U2X  [SOT143-4-48]  68.58 62.74 180 top
U32  PRTR5V0U2X  [SOT143-4-48]  68.58 72.77 180 top
U33  PRTR5V0U2X  [SOT143-4-48]  68.58 76.83 180 top
V-TS  TEST POINT SMD circle 35 mils  [TP28]  47.37 82.42 0 top
Y1  32.768KHZ  [X2-3215-008]  51.44 69.47 90 top
Y2  NC  [X4-2520-010]  50.8 74.55 90 top
Y3  24MHz-3225  [X4-3225-007]  52.07 79.63 90 top
Y4  NC  [X4-3225-010]  52.07 85.34 90 top
Y5  12MHz  [X4-2520-010]  67.31 100.2 180 top

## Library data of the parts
C1-C180 C187-C234 C238-C242 C244-C246 C256-C274 = CAP NP
C243 C247-C255 = CAP POL
D1 = MM5Z5V6ST1G
F1 = 3A-12V
FB1-FB8 = FB
GPIO25 V-TS = TEST_POINT_ SMD_circle_35mils
J1 J5 J8 = CON2X8
J2 J6 J11 J13 = type-c-smd
J3 = TH243-G60S-W0R01
J4 = 30PIN_CONNECT_2D54MM_FPC
J7 = PJ35367
J9 = Flash-EXT
J10 = 2x15PIN_2P54
J12 = CON10
J15 = CON6
K1 = KH-6X6X8H-ZJ
K2 = TS-KG07U
K3 = SK12D07VG3
L1-L3 L6 L9 L10 = INDUCTOR
LED1 = LED
M1-M6 = M3
Q1 = YJL2301C
Q2 = 2N7002
R1-R6 R8 R10 R12-R17 R22 R25-R30 R33 R34 R47 R50-R52 R55 R64 R77 R79 R81 R83 R85 R87 R89 R91-R128 R148 R179-R184 R208 R217 R219-R221 R224 R233 R245 = RESISTOR: signal model: RESISTOR_R0402_0R_0R
R7 R11 R53 R54 R59 R65 R198 R229 R232 R246 R248-R251 = RESISTOR: signal model: RESISTOR_R0402_NC_NC
R9 R31 R137 R145 R195 R211 R213 R215 R230 = Resistor
R18-R21 R23 R24 R32 R35-R46 R48 R49 R56-R58 R60-R63 R66-R76 R78 R80 R82 R84 R86 R88 R90 R129-R136 R138-R144 R146 R147 R149-R172 R174-R178 R185-R194 R196 R197 R199-R207 R209 R210 R212 R214 R218 R222 R223 R234-R243 R252-R267 = RESISTOR
R244 = Resistor: signal model: RESISTOR_R0402_0R_0R
SW1 = SW_SMD_2P54
TP1-TP24 = T POINT S
TVS1-TVS14 = DIODE_TVS_BIDIR
U1 = K230 USIP 13M2
U2 U8 U9 U12-U15 U29 = IC_LDO_TLV758P
U3 U6 = DIO7002AST5
U4 = CONN_MICRO_SDCARD_9P
U5 = NT6CL128M32DM-H0
U7 = MSM381ACT001
U10 = TPS7A7401DSDR
U11 = TPS74801DRC
U16 U25 = SGM4574YUQN12G
U17 U20 U21 = SY8003EDFC
U18 = SY8876DFC
U22-U24 U31-U33 = PRTR5V0U2X
U26 = FT2232HQ
U27 U28 = TPS628681A
U30 = KLM4G1FETE-B041
Y1 = CRYSTAL_2
Y2 Y4 = OSC_4
Y3 Y5 = CRYSTAL_4

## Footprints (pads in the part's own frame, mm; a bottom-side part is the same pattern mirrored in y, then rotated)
AUDIO-PJ3536-7-197
  round 1.219 hole 1.219 unplated: (0,3.4) (0,-3.6)
  rect 2.286x1.27 smd: 1(-3.25,3) 2(-3.25,0.1) 3(-3.25,-2.8) 4(3.25,-3.1) 6(3.25,1.9) 7(3.25,-1) 8(-3.25,-5.1)
BBGA390-065-1313-020
  round 0.305 smd: A2(-5.525,6.175) A3(-4.875,6.175) A4(-4.225,6.175) A5(-3.575,6.175) A6(-2.925,6.175) A7(-2.275,6.175) A8(-1.625,6.175) A9(-0.975,6.175) A10(-0.325,6.175) A11(0.325,6.175) A12(0.975,6.175) A13(1.625,6.175) A14(2.275,6.175) A15(2.925,6.175) A16(3.575,6.175) A17(4.225,6.175) A18(4.875,6.175) A19(5.525,6.175) A20(6.175,6.175) B1(-6.175,5.525) B2(-5.525,5.525) B3(-4.875,5.525) B4(-4.225,5.525) B5(-3.575,5.525) B6(-2.925,5.525) B7(-2.275,5.525) B8(-1.625,5.525) B9(-0.975,5.525) B10(-0.325,5.525) B11(0.325,5.525) B12(0.975,5.525) B13(1.625,5.525) B14(2.275,5.525) B15(2.925,5.525) B16(3.575,5.525) B17(4.225,5.525) B18(4.875,5.525) B19(5.525,5.525) B20(6.175,5.525) C1(-6.175,4.875) C2(-5.525,4.875) C3(-4.875,4.875) C4(-4.225,4.875) C5(-3.575,4.875) C6(-2.925,4.875) C7(-2.275,4.875) C8(-1.625,4.875) C9(-0.975,4.875) C10(-0.325,4.875) C11(0.325,4.875) C12(0.975,4.875) C13(1.625,4.875) C14(2.275,4.875) C15(2.925,4.875) C16(3.575,4.875) C17(4.225,4.875) C18(4.875,4.875) C19(5.525,4.875) C20(6.175,4.875) D1(-6.175,4.225) D2(-5.525,4.225) D3(-4.875,4.225) D4(-4.225,4.225) D5(-3.575,4.225) D6(-2.925,4.225) D7(-2.275,4.225) D8(-1.625,4.225) D9(-0.975,4.225) D10(-0.325,4.225) D11(0.325,4.225) D12(0.975,4.225) D13(1.625,4.225) D14(2.275,4.225) D15(2.925,4.225) D16(3.575,4.225) D17(4.225,4.225) D18(4.875,4.225) D19(5.525,4.225) D20(6.175,4.225) E1(-6.175,3.575) E2(-5.525,3.575) E3(-4.875,3.575) E4(-4.225,3.575) E6(-2.925,3.575) E7(-2.275,3.575) E8(-1.625,3.575) E9(-0.975,3.575) E10(-0.325,3.575) E11(0.325,3.575) E12(0.975,3.575) E13(1.625,3.575) E14(2.275,3.575) E15(2.925,3.575) E16(3.575,3.575) E17(4.225,3.575) E18(4.875,3.575) E19(5.525,3.575) E20(6.175,3.575) F1(-6.175,2.925) F2(-5.525,2.925) F3(-4.875,2.925) F4(-4.225,2.925) F6(-2.925,2.925) F7(-2.275,2.925) F8(-1.625,2.925) F9(-0.975,2.925) F10(-0.325,2.925) F11(0.325,2.925) F12(0.975,2.925) F13(1.625,2.925) F14(2.275,2.925) F15(2.925,2.925) F16(3.575,2.925) F17(4.225,2.925) F18(4.875,2.925) F19(5.525,2.925) F20(6.175,2.925) G1(-6.175,2.275) G2(-5.525,2.275) G3(-4.875,2.275) G4(-4.225,2.275) G5(-3.575,2.275) G6(-2.925,2.275) G7(-2.275,2.275) G8(-1.625,2.275) G9(-0.975,2.275) G10(-0.325,2.275) G11(0.325,2.275) G12(0.975,2.275) G13(1.625,2.275) G14(2.275,2.275) G15(2.925,2.275) G16(3.575,2.275) G17(4.225,2.275) G18(4.875,2.275) G19(5.525,2.275) G20(6.175,2.275) H1(-6.175,1.625) H2(-5.525,1.625) H3(-4.875,1.625) H4(-4.225,1.625) H5(-3.575,1.625) H6(-2.925,1.625) H7(-2.275,1.625) H8(-1.625,1.625) H9(-0.975,1.625) H10(-0.325,1.625) H11(0.325,1.625) H12(0.975,1.625) H13(1.625,1.625) H14(2.275,1.625) H15(2.925,1.625) H16(3.575,1.625) H17(4.225,1.625) H18(4.875,1.625) H19(5.525,1.625) H20(6.175,1.625) J1(-6.175,0.975) J2(-5.525,0.975) J3(-4.875,0.975) J4(-4.225,0.975) J5(-3.575,0.975) J6(-2.925,0.975) J7(-2.275,0.975) J8(-1.625,0.975) J9(-0.975,0.975) J10(-0.325,0.975) J11(0.325,0.975) J12(0.975,0.975) J13(1.625,0.975) J14(2.275,0.975) J15(2.925,0.975) J16(3.575,0.975) J17(4.225,0.975) J18(4.875,0.975) J19(5.525,0.975) J20(6.175,0.975) K1(-6.175,0.325) K2(-5.525,0.325) K3(-4.875,0.325) K4(-4.225,0.325) K5(-3.575,0.325) K6(-2.925,0.325) K7(-2.275,0.325) K8(-1.625,0.325) K9(-0.975,0.325) K10(-0.325,0.325) K11(0.325,0.325) K12(0.975,0.325) K13(1.625,0.325) K14(2.275,0.325) K15(2.925,0.325) K16(3.575,0.325) K17(4.225,0.325) K18(4.875,0.325) K19(5.525,0.325) K20(6.175,0.325) L1(-6.175,-0.325) L2(-5.525,-0.325) L3(-4.875,-0.325) L4(-4.225,-0.325) L5(-3.575,-0.325) L6(-2.925,-0.325) L7(-2.275,-0.325) L8(-1.625,-0.325) L9(-0.975,-0.325) L10(-0.325,-0.325) L11(0.325,-0.325) L12(0.975,-0.325) L13(1.625,-0.325) L14(2.275,-0.325) L15(2.925,-0.325) L16(3.575,-0.325) L17(4.225,-0.325) L18(4.875,-0.325) L19(5.525,-0.325) L20(6.175,-0.325) M1(-6.175,-0.975) M2(-5.525,-0.975) M3(-4.875,-0.975) M4(-4.225,-0.975) M5(-3.575,-0.975) M6(-2.925,-0.975) M7(-2.275,-0.975) M8(-1.625,-0.975) M9(-0.975,-0.975) M10(-0.325,-0.975) M11(0.325,-0.975) M12(0.975,-0.975) M13(1.625,-0.975) M14(2.275,-0.975) M15(2.925,-0.975) M16(3.575,-0.975) M17(4.225,-0.975) M18(4.875,-0.975) M19(5.525,-0.975) M20(6.175,-0.975) N1(-6.175,-1.625) N2(-5.525,-1.625) N3(-4.875,-1.625) N4(-4.225,-1.625) N5(-3.575,-1.625) N6(-2.925,-1.625) N7(-2.275,-1.625) N8(-1.625,-1.625) N9(-0.975,-1.625) N10(-0.325,-1.625) N11(0.325,-1.625) N12(0.975,-1.625) N13(1.625,-1.625) N14(2.275,-1.625) N15(2.925,-1.625) N16(3.575,-1.625) N17(4.225,-1.625) N18(4.875,-1.625) N19(5.525,-1.625) N20(6.175,-1.625) P1(-6.175,-2.275) P2(-5.525,-2.275) P3(-4.875,-2.275) P4(-4.225,-2.275) P5(-3.575,-2.275) P6(-2.925,-2.275) P7(-2.275,-2.275) P8(-1.625,-2.275) P9(-0.975,-2.275) P10(-0.325,-2.275) P11(0.325,-2.275) P12(0.975,-2.275) P13(1.625,-2.275) P14(2.275,-2.275) P15(2.925,-2.275) P16(3.575,-2.275) P17(4.225,-2.275) P18(4.875,-2.275) P19(5.525,-2.275) P20(6.175,-2.275) R1(-6.175,-2.925) R2(-5.525,-2.925) R3(-4.875,-2.925) R6(-2.925,-2.925) R7(-2.275,-2.925) R8(-1.625,-2.925) R9(-0.975,-2.925) R10(-0.325,-2.925) R11(0.325,-2.925) R12(0.975,-2.925) R13(1.625,-2.925) R14(2.275,-2.925) R15(2.925,-2.925) R16(3.575,-2.925) R17(4.225,-2.925) R18(4.875,-2.925) R19(5.525,-2.925) R20(6.175,-2.925) T1(-6.175,-3.575) T2(-5.525,-3.575) T3(-4.875,-3.575) T7(-2.275,-3.575) T8(-1.625,-3.575) T9(-0.975,-3.575) T10(-0.325,-3.575) T11(0.325,-3.575) T12(0.975,-3.575) T13(1.625,-3.575) T14(2.275,-3.575) T15(2.925,-3.575) T16(3.575,-3.575) T17(4.225,-3.575) T18(4.875,-3.575) T19(5.525,-3.575) T20(6.175,-3.575) U1(-6.175,-4.225) U2(-5.525,-4.225) U3(-4.875,-4.225) U6(-2.925,-4.225) U7(-2.275,-4.225) U8(-1.625,-4.225) U9(-0.975,-4.225) U10(-0.325,-4.225) U11(0.325,-4.225) U12(0.975,-4.225) U13(1.625,-4.225) U14(2.275,-4.225) U15(2.925,-4.225) U16(3.575,-4.225) U17(4.225,-4.225) U18(4.875,-4.225) U19(5.525,-4.225) U20(6.175,-4.225) V1(-6.175,-4.875) V2(-5.525,-4.875) V3(-4.875,-4.875) V4(-4.225,-4.875) V5(-3.575,-4.875) V6(-2.925,-4.875) V7(-2.275,-4.875) V8(-1.625,-4.875) V9(-0.975,-4.875) V10(-0.325,-4.875) V11(0.325,-4.875) V12(0.975,-4.875) V13(1.625,-4.875) V14(2.275,-4.875) V15(2.925,-4.875) V16(3.575,-4.875) V17(4.225,-4.875) V18(4.875,-4.875) V19(5.525,-4.875) V20(6.175,-4.875) W1(-6.175,-5.525) W2(-5.525,-5.525) W3(-4.875,-5.525) W4(-4.225,-5.525) W5(-3.575,-5.525) W6(-2.925,-5.525) W7(-2.275,-5.525) W8(-1.625,-5.525) W9(-0.975,-5.525) W10(-0.325,-5.525) W11(0.325,-5.525) W12(0.975,-5.525) W13(1.625,-5.525) W14(2.275,-5.525) W15(2.925,-5.525) W16(3.575,-5.525) W17(4.225,-5.525) W18(4.875,-5.525) W19(5.525,-5.525) W20(6.175,-5.525) Y1(-6.175,-6.175) Y2(-5.525,-6.175) Y3(-4.875,-6.175) Y4(-4.225,-6.175) Y5(-3.575,-6.175) Y6(-2.925,-6.175) Y7(-2.275,-6.175) Y8(-1.625,-6.175) Y9(-0.975,-6.175) Y10(-0.325,-6.175) Y11(0.325,-6.175) Y12(0.975,-6.175) Y13(1.625,-6.175) Y14(2.275,-6.175) Y15(2.925,-6.175) Y16(3.575,-6.175) Y17(4.225,-6.175) Y18(4.875,-6.175) Y19(5.525,-6.175) Y20(6.175,-6.175)
BGA153-050-011010-008
  round 0.254 smd: A1(-3.25,3.25) A2(-2.75,3.25) A3(-2.25,3.25) A4(-1.75,3.25) A5(-1.25,3.25) A6(-0.75,3.25) A7(-0.25,3.25) A8(0.25,3.25) A9(0.75,3.25) A10(1.25,3.25) A11(1.75,3.25) A12(2.25,3.25) A13(2.75,3.25) A14(3.25,3.25) B1(-3.25,2.75) B2(-2.75,2.75) B3(-2.25,2.75) B4(-1.75,2.75) B5(-1.25,2.75) B6(-0.75,2.75) B7(-0.25,2.75) B8(0.25,2.75) B9(0.75,2.75) B10(1.25,2.75) B11(1.75,2.75) B12(2.25,2.75) B13(2.75,2.75) B14(3.25,2.75) C1(-3.25,2.25) C2(-2.75,2.25) C3(-2.25,2.25) C4(-1.75,2.25) C5(-1.25,2.25) C6(-0.75,2.25) C7(-0.25,2.25) C8(0.25,2.25) C9(0.75,2.25) C10(1.25,2.25) C11(1.75,2.25) C12(2.25,2.25) C13(2.75,2.25) C14(3.25,2.25) D1(-3.25,1.75) D2(-2.75,1.75) D3(-2.25,1.75) D4(-1.75,1.75) D12(2.25,1.75) D13(2.75,1.75) D14(3.25,1.75) E1(-3.25,1.25) E2(-2.75,1.25) E3(-2.25,1.25) E5(-1.25,1.25) E6(-0.75,1.25) E7(-0.25,1.25) E8(0.25,1.25) E9(0.75,1.25) E10(1.25,1.25) E12(2.25,1.25) E13(2.75,1.25) E14(3.25,1.25) F1(-3.25,0.75) F2(-2.75,0.75) F3(-2.25,0.75) F5(-1.25,0.75) F10(1.25,0.75) F12(2.25,0.75) F13(2.75,0.75) F14(3.25,0.75) G1(-3.25,0.25) G2(-2.75,0.25) G3(-2.25,0.25) G5(-1.25,0.25) G10(1.25,0.25) G12(2.25,0.25) G13(2.75,0.25) G14(3.25,0.25) H1(-3.25,-0.25) H2(-2.75,-0.25) H3(-2.25,-0.25) H5(-1.25,-0.25) H10(1.25,-0.25) H12(2.25,-0.25) H13(2.75,-0.25) H14(3.25,-0.25) J1(-3.25,-0.75) J2(-2.75,-0.75) J3(-2.25,-0.75) J5(-1.25,-0.75) J10(1.25,-0.75) J12(2.25,-0.75) J13(2.75,-0.75) J14(3.25,-0.75) K1(-3.25,-1.25) K2(-2.75,-1.25) K3(-2.25,-1.25) K5(-1.25,-1.25) K6(-0.75,-1.25) K7(-0.25,-1.25) K8(0.25,-1.25) K9(0.75,-1.25) K10(1.25,-1.25) K12(2.25,-1.25) K13(2.75,-1.25) K14(3.25,-1.25) L1(-3.25,-1.75) L2(-2.75,-1.75) L3(-2.25,-1.75) L12(2.25,-1.75) L13(2.75,-1.75) L14(3.25,-1.75) M1(-3.25,-2.25) M2(-2.75,-2.25) M3(-2.25,-2.25) M4(-1.75,-2.25) M5(-1.25,-2.25) M6(-0.75,-2.25) M7(-0.25,-2.25) M8(0.25,-2.25) M9(0.75,-2.25) M10(1.25,-2.25) M11(1.75,-2.25) M12(2.25,-2.25) M13(2.75,-2.25) M14(3.25,-2.25) N1(-3.25,-2.75) N2(-2.75,-2.75) N3(-2.25,-2.75) N4(-1.75,-2.75) N5(-1.25,-2.75) N6(-0.75,-2.75) N7(-0.25,-2.75) N8(0.25,-2.75) N9(0.75,-2.75) N10(1.25,-2.75) N11(1.75,-2.75) N12(2.25,-2.75) N13(2.75,-2.75) N14(3.25,-2.75) P1(-3.25,-3.25) P2(-2.75,-3.25) P3(-2.25,-3.25) P4(-1.75,-3.25) P5(-1.25,-3.25) P6(-0.75,-3.25) P7(-0.25,-3.25) P8(0.25,-3.25) P9(0.75,-3.25) P10(1.25,-3.25) P11(1.75,-3.25) P12(2.25,-3.25) P13(2.75,-3.25) P14(3.25,-3.25)
BGA178-080065-120115-008
  round 0.279 smd: A1(-4.801,5.2) A2(-4,5.2) A3(-3.2,5.2) A4(-2.4,5.2) A5(-1.6,5.2) A6(-0.8,5.2) A8(0.8,5.2) A9(1.6,5.2) A10(2.4,5.2) A11(3.2,5.2) A12(4,5.2) A13(4.801,5.2) B1(-4.801,4.55) B2(-4,4.55) B3(-3.2,4.55) B4(-2.4,4.55) B5(-1.6,4.55) B6(-0.8,4.55) B8(0.8,4.55) B9(1.6,4.55) B10(2.4,4.55) B11(3.2,4.55) B12(4,4.55) B13(4.801,4.55) C2(-4,3.9) C3(-3.2,3.9) C4(-2.4,3.9) C5(-1.6,3.9) C6(-0.8,3.9) C8(0.8,3.9) C9(1.6,3.9) C10(2.4,3.9) C11(3.2,3.9) C12(4,3.9) D2(-4,3.25) D3(-3.2,3.25) D4(-2.4,3.25) D5(-1.6,3.25) D6(-0.8,3.25) D8(0.8,3.25) D9(1.6,3.25) D10(2.4,3.25) D11(3.2,3.25) D12(4,3.25) E2(-4,2.6) E3(-3.2,2.6) E4(-2.4,2.6) E5(-1.6,2.6) E6(-0.8,2.6) E8(0.8,2.6) E9(1.6,2.6) E10(2.4,2.6) E11(3.2,2.6) E12(4,2.6) F2(-4,1.95) F3(-3.2,1.95) F4(-2.4,1.95) F5(-1.6,1.95) F6(-0.8,1.95) F8(0.8,1.95) F9(1.6,1.95) F10(2.4,1.95) F11(3.2,1.95) F12(4,1.95) G2(-4,1.3) G3(-3.2,1.3) G4(-2.4,1.3) G5(-1.6,1.3) G6(-0.8,1.3) G8(0.8,1.3) G9(1.6,1.3) G10(2.4,1.3) G11(3.2,1.3) G12(4,1.3) H2(-4,0.65) H3(-3.2,0.65) H4(-2.4,0.65) H5(-1.6,0.65) H6(-0.8,0.65) H8(0.8,0.65) H9(1.6,0.65) H10(2.4,0.65) H11(3.2,0.65) H12(4,0.65) J2(-4,0) J3(-3.2,0) J4(-2.4,0) J5(-1.6,0) J6(-0.8,0) J8(0.8,0) J9(1.6,0) J10(2.4,0) J11(3.2,0) J12(4,0) K2(-4,-0.65) K3(-3.2,-0.65) K4(-2.4,-0.65) K5(-1.6,-0.65) K6(-0.8,-0.65) K8(0.8,-0.65) K9(1.6,-0.65) K10(2.4,-0.65) K11(3.2,-0.65) K12(4,-0.65) L2(-4,-1.3) L3(-3.2,-1.3) L4(-2.4,-1.3) L5(-1.6,-1.3) L6(-0.8,-1.3) L8(0.8,-1.3) L9(1.6,-1.3) L10(2.4,-1.3) L11(3.2,-1.3) L12(4,-1.3) M2(-4,-1.95) M3(-3.2,-1.95) M4(-2.4,-1.95) M5(-1.6,-1.95) M6(-0.8,-1.95) M8(0.8,-1.95) M9(1.6,-1.95) M10(2.4,-1.95) M11(3.2,-1.95) M12(4,-1.95) N2(-4,-2.6) N3(-3.2,-2.6) N4(-2.4,-2.6) N5(-1.6,-2.6) N6(-0.8,-2.6) N8(0.8,-2.6) N9(1.6,-2.6) N10(2.4,-2.6) N11(3.2,-2.6) N12(4,-2.6) P2(-4,-3.25) P3(-3.2,-3.25) P4(-2.4,-3.25) P5(-1.6,-3.25) P6(-0.8,-3.25) P8(0.8,-3.25) P9(1.6,-3.25) P10(2.4,-3.25) P11(3.2,-3.25) P12(4,-3.25) R2(-4,-3.9) R3(-3.2,-3.9) R4(-2.4,-3.9) R5(-1.6,-3.9) R6(-0.8,-3.9) R8(0.8,-3.9) R9(1.6,-3.9) R10(2.4,-3.9) R11(3.2,-3.9) R12(4,-3.9) T1(-4.801,-4.55) T2(-4,-4.55) T3(-3.2,-4.55) T4(-2.4,-4.55) T5(-1.6,-4.55) T6(-0.8,-4.55) T8(0.8,-4.55) T9(1.6,-4.55) T10(2.4,-4.55) T11(3.2,-4.55) T12(4,-4.55) T13(4.801,-4.55) U1(-4.801,-5.2) U2(-4,-5.2) U3(-3.2,-5.2) U4(-2.4,-5.2) U5(-1.6,-5.2) U6(-0.8,-5.2) U8(0.8,-5.2) U9(1.6,-5.2) U10(2.4,-5.2) U11(3.2,-5.2) U12(4,-5.2) U13(4.801,-5.2)
BTB2X30-050-F-SMD
  round 0.61 hole 0.61 unplated: (-8.3,1.5) (8.3,1.5)
  rect 0.305x1.651 smd: 1(-7.252,-1.825) 2(-7.252,1.825) 3(-6.752,-1.825) 4(-6.752,1.825) 5(-6.252,-1.825) 6(-6.252,1.825) 7(-5.752,-1.825) 8(-5.752,1.825) 9(-5.251,-1.825) 10(-5.251,1.825) 11(-4.751,-1.825) 12(-4.751,1.825) 13(-4.251,-1.825) 14(-4.251,1.825) 15(-3.751,-1.825) 16(-3.751,1.825) 17(-3.251,-1.825) 18(-3.251,1.825) 19(-2.751,-1.825) 20(-2.751,1.825) 21(-2.251,-1.825) 22(-2.251,1.825) 23(-1.751,-1.825) 24(-1.751,1.825) 25(-1.25,-1.825) 26(-1.25,1.825) 27(-0.75,-1.825) 28(-0.75,1.825) 29(-0.25,-1.825) 30(-0.25,1.825) 31(0.25,-1.825) 32(0.25,1.825) 33(0.75,-1.825) 34(0.75,1.825) 35(1.25,-1.825) 36(1.25,1.825) 37(1.75,-1.825) 38(1.75,1.825) 39(2.25,-1.825) 40(2.25,1.825) 41(2.751,-1.825) 42(2.751,1.825) 43(3.251,-1.825) 44(3.251,1.825) 45(3.751,-1.825) 46(3.751,1.825) 47(4.251,-1.825) 48(4.251,1.825) 49(4.751,-1.825) 50(4.751,1.825) 51(5.251,-1.825) 52(5.251,1.825) 53(5.751,-1.825) 54(5.751,1.825) 55(6.251,-1.825) 56(6.251,1.825) 57(6.752,-1.825) 58(6.752,1.825) 59(7.252,-1.825) 60(7.252,1.825)
C0402
  rect 0.635x0.508 smd: 1(-0.508,0) 2(0.508,0)
C0603
  rect 0.889x0.813 smd: 1(-0.762,0) 2(0.762,0)
C1010_8383_6666
  rect 1.27x4.928 smd: 1(0,-3.352) 2(0,3.352)
C1206
  rect 1.397x1.651 smd: 1(-1.397,0) 2(1.397,0)
CARD-MICRO-SD-9-80
  round 1.016 hole 1.016 unplated: (-4.928,-2.65) (3.072,-2.65)
  rect 0.711x1.6 smd: 1(2.221,7.926) 2(1.121,7.926) 3(0.022,7.926) 4(-1.078,7.926) 5(-2.179,7.926) 6(-3.278,7.926) 7(-4.378,7.926) 8(-5.479,7.926) 9(-6.579,7.926)
  rect 1.016x2.032 smd: 10(-7.931,7.35) 12(7.874,-2.25) 13(-7.931,-2.25)
  rect 1.397x1.6 smd: 11(6.821,7.35)
DFN6-065-0202-008-N
  rect 0.457x0.381 smd: 1(-0.975,0.65) 2(-0.975,0) 3(-0.975,-0.65) 4(0.975,-0.65) 5(0.975,0) 6(0.975,0.65)
  rect 0.991x1.6 smd: 7(0,0)
DFN8-050-0202-006
  custom 0.152x0.152 smd: 1(-0.753,-0.102) 4(0.753,-0.102)
  rect 0.279x1.524 smd: 2(-0.237,-0.457) 3(0.237,-0.457)
  rect 0.305x0.61 smd: 5(0.75,0.914) 6(0.25,0.914) 7(-0.25,0.914) 8(-0.75,0.914)
DFN10-050-0303-010-N
  rect 0.762x0.305 smd: 1(-1.4,1) 2(-1.4,0.5) 3(-1.4,0) 4(-1.4,-0.5) 5(-1.4,-1) 6(1.4,-1) 7(1.4,-0.5) 8(1.4,0) 9(1.4,0.5) 10(1.4,1)
  custom 0.412x0.412 smd: 11(0,0)
DSW3-087044-047-H
  oval 1.778x2.54 hole 1.016x1.778: (-4.15,0) (4.15,0)
  rect 1.524x1.524 hole 1.016: 1(-2,0)
  round 1.524 hole 1.016: 2(0,0) 3(2,0)
DSW4-KH-6X6X7H-ZJ
  round 1.778 hole 1.143: 1(-2.25,-1.25) 2(2.25,-1.25)
  round 1.905 hole 1.397: 3(-3.5,1.25) 4(3.5,1.25)
F1206
  rect 1.397x1.651 smd: 1(-1.397,0) 2(1.397,0)
FB0402
  rect 0.635x0.508 smd: 1(-0.508,0) 2(0.508,0)
FPC30-005-0520-75
  rect 0.305x1.016 smd: 1(7.248,0) 2(6.748,0) 3(6.248,0) 4(5.749,0) 5(5.249,0) 6(4.749,0) 7(4.249,0) 8(3.749,0) 9(3.249,0) 10(2.749,0) 11(2.249,0) 12(1.75,0) 13(1.25,0) 14(0.75,0) 15(0.25,0) 16(-0.25,0) 17(-0.75,0) 18(-1.25,0) 19(-1.75,0) 20(-2.249,0) 21(-2.749,0) 22(-3.249,0) 23(-3.749,0) 24(-4.249,0) 25(-4.749,0) 26(-5.249,0) 27(-5.749,0) 28(-6.248,0) 29(-6.748,0) 30(-7.248,0)
  rect 2.032x1.321 smd: 31(-9.548,-2.7) 32(9.548,-2.7)
